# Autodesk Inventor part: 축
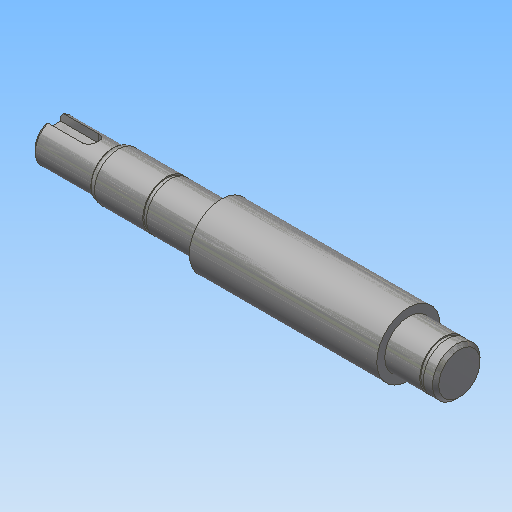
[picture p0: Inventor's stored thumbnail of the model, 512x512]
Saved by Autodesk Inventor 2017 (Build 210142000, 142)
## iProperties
Created: 2015-12
Part Number: 축
Material: 강철, 연강
Document SubType Name: Modeling
Designer: mduedu
Density: 7.86 g/cm^3
Appearance: 강철
Author: mduedu
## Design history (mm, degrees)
sketch "스케치1"
  geometry: L1 (-64, 0)-(64, 0); L2 (-64, 0)-(-64, 6.5); L3 (-64, 6.5)-(-45, 6.5); L4 (-45, 7)-(-44.134, 7.5); L5 (-44.134, 7.5)-(-11, 7.5); L6 (-11, 7.5)-(-11, 10); L7 (-11, 10)-(48, 10); L8 (48, 10)-(48, 7.5); L9 (48, 7.5)-(64, 7.5); L10 (64, 7.5)-(64, 0); L11 (-45, 6.5)-(-45, 7); 2 further points
  constraints: 22 end point, 6 parallel, 2 perpendicular, 1 coincident, 1 horizontal, 1 midpoint, 1 vertical
  dimensions: "d0" = 13 diameter of L3 L1; "d2" = 15 diameter of L5 L1; "d3" = 20 diameter of L7 L1; "d5" = 15 diameter of L9 L1; "d6" = 128 distance of L1.start L1.end; "d7" = 19 distance of L2.end L3.end; "d8" = 34 distance from line of L6 L3.end; "d9" = 59 distance of L6.end L7.end; "d41" = 14 diameter of L4.start L1; "d42" = 30 deg angle of L4 L3
revolve "회전1" sketch "스케치1" stored, may be unused: angle "d11" = 90 deg
node "작업 평면1"
node "작업 평면2"
sketch "스케치3"
  geometry: L1 (9.5, -2.5)-(-2.5, -2.5); L2 (-2.5, 2.5)-(9.5, 2.5); L3 (9.5, 2.5)-(9.5, -2.5); L4 (9.5, 6.5)-(9.5, -6.5) reference; A1 r 2.5 centre (-2.5, 0) between (-2.5, 2.5) and (-2.5, -2.5); 1 further point
  constraints: 6 end point, 2 point on circle, 2 tangent, 1 centre point, 1 collinear, 1 horizontal, 1 horizontal alignment, 1 parallel
  dimensions: "d17" = 5 distance of L2.end L1.start; "d19" = 12 distance from line of A1.centre L3
extrude "돌출2" cut sketch "스케치3" distance "d20" = 3; taper "d21" = 0 deg
chamfer "모따기1" distance "d22" = 1; stored, may be unused: second distance "d23" = 2, angle "d24" = 45 deg
fillet "모깎기1" dims "d25" = 3
sketch "스케치4"
  geometry: L1 (-11, -10)-(-11, 10) reference; L2 (-11, 0)-(0, 0); L3 (-28.15, 12.15)-(-27, 12.15); L4 (-27, 12.15)-(-27, 7.15); L5 (-27, 7.15)-(-28.15, 7.15); L6 (-28.15, 7.15)-(-28.15, 12.15); L7 (59, 12.15)-(60.15, 12.15); L8 (60.15, 12.15)-(60.15, 7.15); L9 (60.15, 7.15)-(59, 7.15); L10 (59, 7.15)-(59, 12.15); L11 (64, -7.5)-(64, 7.5) reference
  constraints: 18 end point, 4 parallel, 2 horizontal, 2 perpendicular, 1 midpoint
  dimensions: "d26" = 16 distance between parallel lines of L4 L1; "d27" = 1.15 distance of L3.start L3.end; "d28" = 14.3 diameter of L5 L2; "d29" = 5 distance of L3.end L4.end; "d30" = 1.15 distance of L7.start L7.end; "d31" = 5 distance of L7.end L8.end; "d32" = 5 distance between parallel lines of L10 L11; "d33" = 14.3 diameter of L9 L2
revolve "회전2" sketch "스케치4" stored, may be unused: angle "d34" = 90 deg
chamfer "모따기2" distance "d35" = 1; stored, may be unused: second distance "d36" = 2, angle "d37" = 45 deg
sketch "스케치5"
  geometry: 2 further points
  constraints: 1 coincident
sketch "스케치6"
  geometry: 1 further point
hole "구멍1" sketch "스케치6" at (2.5, -3.5) diameter "d43" = 4.917; stored, may be unused: countersink angle "d47" = 90 deg, drill point angle "d49" = 120 deg; dims "d44" = 14, "d45" = 4, "d46" = 2, "d48" = 17
node "솔리드1"
other parameters: "d12" = -15.5
